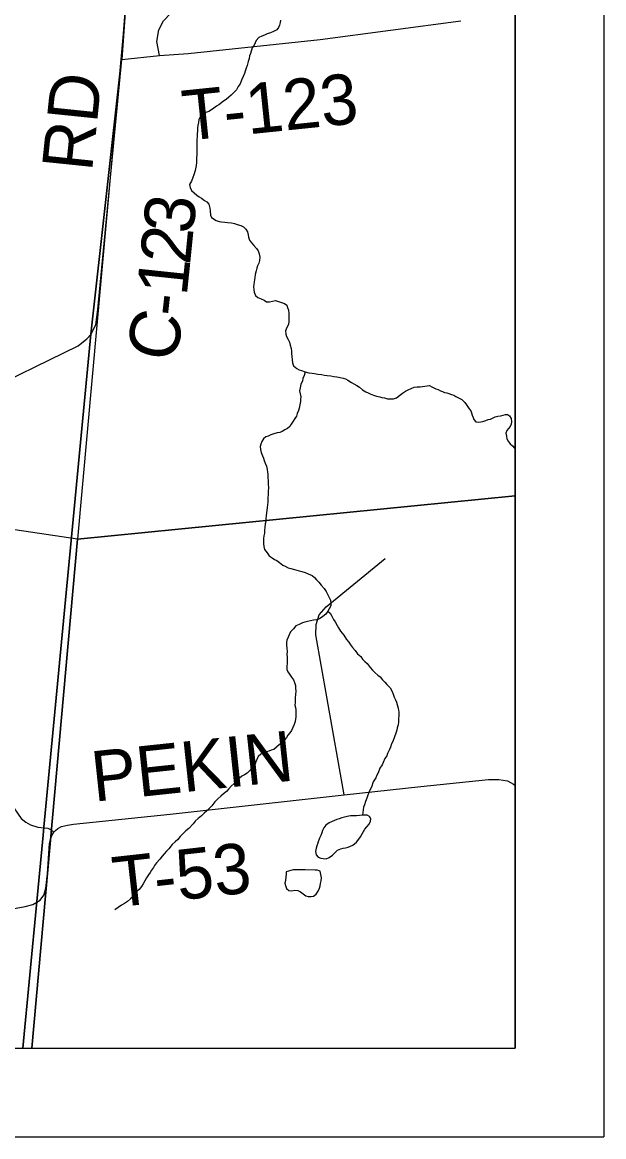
# Model space of a CAD drawing. Extents: x -7.3 to 34, y 0 to 22.
# Drawn here: x 8.344 to 9, y 14 to 15.258 of the extents above; entities that cross this region are included whole.
import ezdxf

# ---------------------------------------------------------------- set-up
doc = ezdxf.new("R2010")
doc.units = 0
for name, color, linetype in [('GM_X_Corporation', 7, 'Continuous'), ('GM_X_County_Road', 7, 'Continuous'), ('GM_X_County_Road_Text', 7, 'Continuous'), ('GM_X_Minor_Lake', 7, 'Continuous'), ('GM_X_Minor_River', 7, 'Continuous'), ('GM_X_Township_Road', 7, 'Continuous'), ('GM_X_Township_Road_Text', 7, 'Continuous'), ('SH_Data', 7, 'Continuous')]:
    doc.layers.add(name, color=color, linetype=linetype)

msp = doc.modelspace()

# ---------------------------------------------------------------- linework, layer by layer
at = {"layer": 'GM_X_Corporation'}
for points in [[(4.3152, 15.5847), (4.2701, 15.1232), (4.2655, 15.0758), (4.2591, 15.0066), (4.246, 14.8644), (4.233, 14.7229), (4.2199, 14.5807), (4.1921, 14.279), (4.1756, 14.1), (8.9, 14.1), (8.9, 19.7858)], [(8.4601, 15.2687), (8.4562, 15.2161), (8.4214, 14.9056), (8.3685, 14.3492), (8.3676, 14.3403), (8.3604, 14.2653), (8.3447, 14.1), (8.9, 14.1), (8.9, 19.3924)], [(4.3152, 15.5847), (4.2701, 15.1232), (4.2655, 15.0758), (4.2591, 15.0066), (4.246, 14.8644), (4.233, 14.7229), (4.2199, 14.5807), (4.1921, 14.279), (4.1756, 14.1), (8.3447, 14.1), (8.3604, 14.2653), (8.3676, 14.3403), (8.3685, 14.3492), (8.4214, 14.9056), (8.4562, 15.2161), (8.4601, 15.2687)]]:
    msp.add_lwpolyline(points, dxfattribs=at)
for points in [[(7.4799, 15.8457), (8.4992, 15.7029), (8.4066, 14.6743), (7.3939, 14.8252)], [(8.9, 14.7231), (8.9, 15.7443), (8.4992, 15.7029), (8.4066, 14.6743)], [(7.3299, 14.1), (8.355, 14.1), (8.4066, 14.6743), (7.3939, 14.8252), (7.354, 14.3269)], [(8.355, 14.1), (8.9, 14.1), (8.9, 14.7231), (8.4066, 14.6743)]]:
    msp.add_lwpolyline(points, close=True, dxfattribs=at)
at = {"layer": 'GM_X_County_Road'}
for points in [[(8.4599, 15.2763), (8.4602, 15.2754), (8.4603, 15.2681), (8.4564, 15.2156)], [(7.8704, 14.526), (7.876, 14.5324), (7.8781, 14.5381), (7.8939, 14.7215), (7.8968, 14.7318), (7.9004, 14.737), (7.9057, 14.74), (7.9114, 14.7411), (7.9173, 14.7411), (7.9598, 14.7363), (8.0106, 14.7293), (8.0376, 14.7266), (8.0458, 14.7274), (8.0546, 14.7289), (8.0834, 14.7403), (8.2135, 14.7969), (8.293, 14.8366), (8.4073, 14.8926), (8.4169, 14.9004), (8.4216, 14.9051), (8.4272, 14.9163), (8.4292, 14.9335), (8.4564, 15.2156)], [(8.3687, 14.2737), (8.3706, 14.2803), (8.3725, 14.2967), (8.3749, 14.331), (8.376, 14.3352), (8.3776, 14.3397), (8.3799, 14.3435)], [(8.0558, 14.2031), (8.1811, 14.2279), (8.3163, 14.254), (8.3475, 14.2599), (8.3559, 14.2622), (8.3606, 14.2648), (8.3644, 14.267), (8.3683, 14.2726), (8.3687, 14.2737)]]:
    msp.add_lwpolyline(points, dxfattribs=at)
at = {"layer": 'GM_X_Minor_Lake'}
for points in [[(8.6777, 14.3315), (8.6775, 14.3311), (8.6763, 14.3281), (8.6755, 14.3255), (8.675, 14.3217), (8.6757, 14.3182), (8.6779, 14.3155), (8.681, 14.3143), (8.6836, 14.3139), (8.687, 14.3134), (8.6905, 14.3149), (8.6939, 14.3178), (8.697, 14.3208), (8.6997, 14.3234), (8.7036, 14.3249), (8.7062, 14.3256), (8.7089, 14.3259), (8.7116, 14.3266), (8.7142, 14.3277), (8.7169, 14.3291), (8.7212, 14.3325), (8.7239, 14.3358), (8.7255, 14.3384), (8.7275, 14.3418), (8.729, 14.3444), (8.7306, 14.3471), (8.7329, 14.3497), (8.7353, 14.3527), (8.7369, 14.356), (8.7373, 14.3587), (8.7358, 14.3614), (8.7332, 14.363), (8.7279, 14.3627)], [(8.7279, 14.3627), (8.7245, 14.3624), (8.7211, 14.3621), (8.7177, 14.3622), (8.7142, 14.3619), (8.7108, 14.3612), (8.7078, 14.3605), (8.7047, 14.3598), (8.7016, 14.3587), (8.699, 14.358), (8.6963, 14.3569), (8.6936, 14.3558), (8.6902, 14.354), (8.6867, 14.3514), (8.6844, 14.3484), (8.6828, 14.3454), (8.682, 14.3428), (8.6808, 14.3398), (8.6796, 14.3368), (8.6777, 14.3315)], [(8.6419, 14.2988), (8.6419, 14.2962), (8.6414, 14.2928), (8.641, 14.2894), (8.6405, 14.286), (8.6412, 14.2833), (8.6423, 14.2802), (8.6449, 14.2779), (8.6483, 14.2774), (8.6517, 14.2781), (8.6551, 14.278), (8.6578, 14.2765), (8.6611, 14.2741), (8.6641, 14.2718), (8.6667, 14.2709), (8.6701, 14.2709), (8.6728, 14.2716), (8.6755, 14.2738), (8.6779, 14.2772), (8.6795, 14.2805), (8.6803, 14.2832), (8.6807, 14.2858), (8.6812, 14.2889), (8.6816, 14.2923), (8.6809, 14.2957), (8.6803, 14.2995), (8.6769, 14.3007), (8.6747, 14.3008)], [(8.6747, 14.3008), (8.6632, 14.301), (8.6598, 14.3011), (8.6564, 14.3012), (8.653, 14.3013), (8.6496, 14.3013), (8.6419, 14.2988)]]:
    msp.add_lwpolyline(points, dxfattribs=at)
at = {"layer": 'GM_X_Minor_River'}
for points in [[(8.6356, 15.2598), (8.6351, 15.2571), (8.6343, 15.2541), (8.6331, 15.2515), (8.6312, 15.2488), (8.6277, 15.247), (8.6243, 15.2456), (8.6204, 15.2445), (8.6174, 15.2431), (8.6143, 15.242), (8.6109, 15.2402), (8.6081, 15.2368), (8.6057, 15.2315), (8.6034, 15.2285), (8.6014, 15.2221), (8.6005, 15.2195), (8.6001, 15.2168), (8.5989, 15.2134), (8.598, 15.2089), (8.5968, 15.2059), (8.5956, 15.2025), (8.5948, 15.1999), (8.5932, 15.1965), (8.5916, 15.1923), (8.59, 15.1882), (8.5877, 15.1852), (8.5857, 15.1814), (8.583, 15.1788)], [(8.583, 15.1788), (8.5799, 15.1751), (8.5772, 15.1729), (8.5741, 15.1703), (8.571, 15.1685), (8.566, 15.1644), (8.5633, 15.1629), (8.5602, 15.1607), (8.5575, 15.1589), (8.5544, 15.157), (8.5502, 15.1552), (8.5475, 15.1541), (8.5452, 15.1512), (8.5432, 15.1478), (8.5428, 15.1444), (8.5423, 15.141), (8.5419, 15.1383), (8.5418, 15.1349), (8.5414, 15.1315), (8.5413, 15.1285), (8.5412, 15.1247), (8.5412, 15.122), (8.5411, 15.1186), (8.541, 15.1159), (8.5409, 15.1121), (8.5412, 15.1076), (8.5408, 15.1049), (8.5407, 15.1019), (8.5407, 15.0992), (8.5402, 15.0958), (8.5393, 15.0901), (8.5377, 15.0852), (8.5365, 15.0822), (8.5349, 15.0784), (8.5329, 15.0743), (8.5336, 15.0709), (8.535, 15.0678), (8.538, 15.0651), (8.541, 15.0624), (8.5436, 15.0604), (8.5462, 15.0592), (8.5496, 15.0565), (8.5522, 15.0549), (8.5544, 15.0522), (8.5558, 15.0476), (8.5562, 15.0446), (8.5564, 15.04), (8.5575, 15.0373), (8.5627, 15.0338), (8.5661, 15.0329), (8.5688, 15.0325), (8.5726, 15.032), (8.5756, 15.0316), (8.5801, 15.0311), (8.5835, 15.0303), (8.5865, 15.0295), (8.5907, 15.0282), (8.5937, 15.0266), (8.5963, 15.0239), (8.5981, 15.0212), (8.5988, 15.0178), (8.5995, 15.0151), (8.6006, 15.0117), (8.6028, 15.0086), (8.6054, 15.0055), (8.6083, 15.0024), (8.6102, 14.9997), (8.6112, 14.9962), (8.6123, 14.9924), (8.6118, 14.9886), (8.611, 14.9856), (8.6094, 14.9826), (8.6086, 14.98), (8.6078, 14.977), (8.6069, 14.9728), (8.6065, 14.969), (8.6056, 14.9648), (8.6052, 14.9618), (8.6051, 14.9592), (8.6054, 14.9557), (8.6057, 14.9531), (8.6072, 14.9492), (8.6098, 14.9469), (8.6135, 14.9453), (8.6169, 14.9441), (8.6195, 14.9421), (8.623, 14.942), (8.6264, 14.9427), (8.6298, 14.9434), (8.6332, 14.9426), (8.6366, 14.9414), (8.64, 14.9402), (8.6426, 14.9382), (8.6433, 14.9355), (8.6444, 14.9328), (8.645, 14.929), (8.645, 14.9256), (8.6448, 14.9199), (8.6444, 14.9165), (8.6424, 14.9131), (8.6412, 14.9094)], [(8.6412, 14.9094), (8.6415, 14.9056), (8.6422, 14.9029), (8.644, 14.8994), (8.6455, 14.8967), (8.6465, 14.8933), (8.6476, 14.8895), (8.6479, 14.8864), (8.6479, 14.8838), (8.6482, 14.8803), (8.6485, 14.8765), (8.6491, 14.8731), (8.6502, 14.87), (8.6539, 14.8669), (8.6566, 14.8653), (8.6592, 14.8645), (8.6633, 14.8629), (8.6675, 14.8621), (8.6713, 14.8616), (8.6739, 14.8612), (8.6777, 14.8603), (8.6815, 14.8599), (8.6849, 14.8594), (8.6879, 14.859), (8.6921, 14.8585), (8.6955, 14.858), (8.6989, 14.8576), (8.7026, 14.8567), (8.706, 14.8559), (8.7087, 14.8551), (8.7113, 14.8535), (8.7154, 14.8511), (8.718, 14.8496), (8.7214, 14.8476), (8.7244, 14.8456), (8.7281, 14.8429), (8.7315, 14.8405), (8.7345, 14.8393), (8.7375, 14.8377), (8.7413, 14.8365), (8.7439, 14.8357), (8.7473, 14.8349), (8.7499, 14.8341), (8.7526, 14.8336), (8.756, 14.8328), (8.7594, 14.8327), (8.7628, 14.8326), (8.7662, 14.8337), (8.7697, 14.8363), (8.7732, 14.8389), (8.7763, 14.8411), (8.7793, 14.8429), (8.7828, 14.8444), (8.7862, 14.8458), (8.7896, 14.8461), (8.7931, 14.846)], [(8.6633, 14.8629), (8.6621, 14.8588), (8.6605, 14.8554), (8.6601, 14.8527), (8.6585, 14.8493), (8.6576, 14.8452), (8.6568, 14.8418), (8.6575, 14.8383), (8.6582, 14.8349), (8.6581, 14.8323), (8.6581, 14.8296), (8.6572, 14.8258), (8.6564, 14.822), (8.6556, 14.8194), (8.6543, 14.816), (8.6535, 14.813), (8.6516, 14.8104), (8.6496, 14.8074), (8.6476, 14.804), (8.6461, 14.8014), (8.6434, 14.7991), (8.6403, 14.7977), (8.6372, 14.7959), (8.6345, 14.7948), (8.6315, 14.7941), (8.628, 14.793), (8.6246, 14.792), (8.6215, 14.7905), (8.6189, 14.7898), (8.6162, 14.7876), (8.6142, 14.7846), (8.6134, 14.7816), (8.6126, 14.7789), (8.6129, 14.7755), (8.6136, 14.7721), (8.615, 14.7682), (8.6161, 14.7655), (8.6171, 14.7629), (8.6182, 14.7602), (8.6197, 14.7567), (8.6203, 14.7529), (8.6207, 14.7499), (8.621, 14.7472), (8.6213, 14.7438), (8.6216, 14.74), (8.6215, 14.7362), (8.6218, 14.7324), (8.6217, 14.7282), (8.6216, 14.7248), (8.6212, 14.721), (8.6211, 14.716), (8.6206, 14.713), (8.6202, 14.71), (8.6201, 14.7066), (8.6197, 14.7039), (8.6192, 14.7005), (8.6188, 14.6975), (8.6187, 14.6941), (8.6182, 14.6914), (8.6178, 14.6876), (8.6173, 14.6846), (8.6173, 14.6812), (8.6168, 14.6781), (8.6164, 14.6751), (8.6163, 14.6721), (8.6163, 14.6694), (8.6166, 14.666), (8.6172, 14.6626), (8.6202, 14.6587), (8.6228, 14.6556), (8.6261, 14.6533), (8.6288, 14.6513), (8.6314, 14.6501), (8.6344, 14.6481), (8.6381, 14.645), (8.6407, 14.6438), (8.6441, 14.6418), (8.6471, 14.641), (8.6513, 14.6402), (8.6539, 14.6394), (8.6565, 14.6385), (8.6596, 14.6377), (8.6633, 14.6365), (8.6667, 14.6353), (8.6712, 14.6333), (8.6738, 14.6309), (8.676, 14.6282), (8.6786, 14.6259), (8.6812, 14.6224), (8.6846, 14.6186), (8.6868, 14.6151), (8.689, 14.6116), (8.6904, 14.6086), (8.6919, 14.6055), (8.6922, 14.6021), (8.6921, 14.599), (8.6905, 14.5956), (8.6889, 14.593), (8.6866, 14.5896), (8.6831, 14.5871), (8.6796, 14.5845)], [(8.7931, 14.846), (8.8035, 14.8475), (8.8061, 14.8463), (8.8083, 14.8451), (8.8106, 14.8439), (8.8132, 14.8431), (8.8159, 14.8415), (8.8181, 14.8407), (8.8204, 14.8399), (8.823, 14.8394), (8.8253, 14.8386), (8.8283, 14.8374), (8.8309, 14.8366), (8.8332, 14.8354), (8.8354, 14.8342), (8.8377, 14.833), (8.8399, 14.8318), (8.8433, 14.8283), (8.8451, 14.826), (8.8469, 14.8236), (8.8484, 14.8213), (8.8502, 14.819), (8.8509, 14.8167), (8.8516, 14.814), (8.8527, 14.8117), (8.8534, 14.8094), (8.8556, 14.8067), (8.8587, 14.8062), (8.8613, 14.8066), (8.8636, 14.8069), (8.8671, 14.8083), (8.8698, 14.8094), (8.8724, 14.8097), (8.8747, 14.8108), (8.8774, 14.8122), (8.8805, 14.8129), (8.8835, 14.8136), (8.8866, 14.8143), (8.8893, 14.815), (8.8916, 14.8149), (8.8938, 14.8133), (8.8956, 14.8103), (8.8959, 14.8068), (8.8958, 14.8042), (8.8946, 14.8015), (8.8927, 14.7993), (8.8907, 14.7967), (8.8895, 14.7937), (8.8902, 14.7906), (8.8909, 14.7876), (8.8923, 14.7849), (8.8945, 14.7818), (8.8971, 14.7794), (8.8993, 14.7771), (8.9, 14.7766)], [(8.6889, 14.593), (8.6915, 14.5907), (8.6934, 14.5872), (8.6952, 14.5838), (8.697, 14.5811), (8.6992, 14.5768), (8.701, 14.5741), (8.7032, 14.5703), (8.7069, 14.566), (8.7098, 14.561), (8.7124, 14.5579), (8.7143, 14.5552), (8.7165, 14.5521), (8.7198, 14.5486), (8.7224, 14.5448), (8.7261, 14.5417), (8.728, 14.539), (8.7305, 14.5363), (8.7332, 14.5339), (8.7365, 14.5293), (8.7391, 14.5266), (8.7417, 14.5239), (8.7454, 14.5207), (8.748, 14.5188), (8.7506, 14.5157), (8.7532, 14.513), (8.7554, 14.5103), (8.7591, 14.5064), (8.7613, 14.5025), (8.7624, 14.4995), (8.7638, 14.496), (8.7653, 14.493), (8.7663, 14.4903), (8.7674, 14.4861), (8.7681, 14.4834), (8.7688, 14.4792), (8.769, 14.4754), (8.7686, 14.4716), (8.7685, 14.4678), (8.7681, 14.4648), (8.7672, 14.4614), (8.7668, 14.4587), (8.7656, 14.4553), (8.764, 14.4512), (8.762, 14.4459), (8.7608, 14.4433), (8.7595, 14.4395), (8.7583, 14.4369), (8.756, 14.4324), (8.7552, 14.4297), (8.7532, 14.4267), (8.7512, 14.4222), (8.75, 14.4196), (8.7476, 14.4158), (8.7456, 14.4106), (8.7441, 14.4079), (8.7429, 14.4049), (8.7401, 14.4004), (8.7381, 14.3944), (8.7361, 14.391), (8.7349, 14.3884), (8.7341, 14.3854), (8.7329, 14.382), (8.7313, 14.3782), (8.7301, 14.3744), (8.7292, 14.3718), (8.7279, 14.3627)], [(8.6796, 14.5845), (8.6762, 14.5834), (8.6728, 14.5827), (8.6693, 14.582), (8.6659, 14.5814), (8.6629, 14.5807), (8.6602, 14.58), (8.6564, 14.5778), (8.6529, 14.5763), (8.6502, 14.573), (8.6467, 14.5696), (8.6451, 14.5662), (8.6439, 14.5636), (8.6427, 14.5602), (8.6423, 14.5575), (8.6422, 14.5541), (8.6425, 14.5515), (8.6428, 14.5473), (8.6427, 14.5446), (8.643, 14.5412), (8.643, 14.5374), (8.6429, 14.5344), (8.6424, 14.5306), (8.6427, 14.5271), (8.6438, 14.5245), (8.6457, 14.5218), (8.6479, 14.5187), (8.6501, 14.5156), (8.6511, 14.5125), (8.6522, 14.5091), (8.6525, 14.506), (8.6528, 14.5026), (8.6524, 14.4988), (8.6519, 14.4954), (8.6518, 14.4928), (8.6518, 14.4901), (8.6517, 14.4871), (8.6524, 14.4844), (8.6527, 14.4817), (8.6527, 14.4787), (8.6526, 14.4737), (8.6525, 14.4711), (8.6521, 14.4684), (8.6509, 14.465), (8.6493, 14.4617), (8.6477, 14.4583), (8.6461, 14.4556), (8.6438, 14.453), (8.6422, 14.4504), (8.6375, 14.4452), (8.6341, 14.4422), (8.631, 14.4396), (8.6279, 14.4371), (8.6248, 14.436), (8.6221, 14.4349), (8.6195, 14.4342), (8.6164, 14.4331), (8.6133, 14.4317), (8.6103, 14.4291), (8.6087, 14.4257), (8.6075, 14.4231), (8.6063, 14.4197), (8.6039, 14.4171), (8.6012, 14.4137), (8.5977, 14.4104), (8.595, 14.4085), (8.5919, 14.4067), (8.5888, 14.4041), (8.5857, 14.4007), (8.583, 14.3985), (8.5796, 14.3955), (8.5768, 14.3922), (8.5745, 14.3896), (8.571, 14.387), (8.5683, 14.3844), (8.5648, 14.3811), (8.5613, 14.3777), (8.5578, 14.3732), (8.5555, 14.3706), (8.5524, 14.3676), (8.5493, 14.3651), (8.5462, 14.3621), (8.5424, 14.3591), (8.5393, 14.3562), (8.5369, 14.3532), (8.5322, 14.3476), (8.5288, 14.345), (8.5249, 14.3413), (8.5222, 14.3387), (8.5198, 14.3353), (8.5167, 14.3327), (8.5133, 14.3297), (8.5094, 14.3249), (8.507, 14.3223), (8.5043, 14.3193), (8.502, 14.3167), (8.4993, 14.3133), (8.4957, 14.3089), (8.4934, 14.3062), (8.4922, 14.3036), (8.4899, 14.3006)], [(8.4899, 14.3006), (8.4883, 14.298), (8.4867, 14.2954), (8.4844, 14.292), (8.4824, 14.2886), (8.4804, 14.2852), (8.4785, 14.2822), (8.4761, 14.2789), (8.4734, 14.2767), (8.4715, 14.2737), (8.4691, 14.2711), (8.4664, 14.2685), (8.4629, 14.2655), (8.4595, 14.2633), (8.456, 14.2611), (8.4522, 14.2585), (8.4487, 14.2559)]]:
    msp.add_lwpolyline(points, dxfattribs=at)
at = {"layer": 'GM_X_Township_Road'}
for points in [[(8.4991, 15.2202), (8.496, 15.236), (8.498, 15.2488), (8.5034, 15.2591), (8.5354, 15.2929), (8.5493, 15.307), (8.5573, 15.3172), (8.5625, 15.3244), (8.5665, 15.3336), (8.5716, 15.3445), (8.5773, 15.3659), (8.5801, 15.376), (8.5821, 15.3838), (8.5838, 15.3896), (8.5863, 15.395), (8.5918, 15.4005), (8.5996, 15.4057), (8.6113, 15.414)], [(8.4564, 15.2156), (8.4991, 15.2202), (8.5311, 15.2224), (8.6803, 15.238), (8.8388, 15.2593)], [(8.7074, 14.3857), (8.6753, 14.5664), (8.6757, 14.5779), (8.6792, 14.5889), (8.6869, 14.5978), (8.7535, 14.6525)], [(8.3974, 14.352), (8.4018, 14.3527), (8.5111, 14.3641), (8.7074, 14.3857), (8.7938, 14.3952), (8.87, 14.4029), (8.8817, 14.403), (8.8915, 14.4016), (8.8984, 14.3977), (8.9, 14.3962)], [(8.2633, 14.3728), (8.2816, 14.3797), (8.2868, 14.3818), (8.2941, 14.3833), (8.3046, 14.3833), (8.3124, 14.3828), (8.3181, 14.3816), (8.3234, 14.3802), (8.3283, 14.3774), (8.3338, 14.3721), (8.3396, 14.3638), (8.343, 14.359), (8.3481, 14.3549), (8.3536, 14.3521), (8.3618, 14.3493), (8.3687, 14.3487), (8.3729, 14.3481), (8.3767, 14.3463), (8.3799, 14.3435)], [(8.3799, 14.3435), (8.3817, 14.3457), (8.3844, 14.3478), (8.3884, 14.35), (8.3952, 14.3517), (8.3974, 14.352)]]:
    msp.add_lwpolyline(points, dxfattribs=at)
at = {"layer": 'SH_Data'}
for p, q in [((9, 21), (9, 14)), ((8.9, 20.9), (8.9, 14.1)), ((2.1, 14.1), (8.9, 14.1)), ((2, 14), (9, 14))]:
    msp.add_line(p, q, dxfattribs=at)

# ---------------------------------------------------------------- texts
at = {"layer": 'GM_X_County_Road_Text'}
for s, height, rotation, p in [('RD', 0.05682, 84.0953, (8.4227, 15.0881)), ('3', 0.0568, 84.3761, (8.5368, 15.0178)), ('2', 0.0568, 84.3036, (8.5333, 14.9829)), ('1', 0.0568, 83.9845, (8.5296, 14.9477)), ('-', 0.0568, 83.5223, (8.5269, 14.924)), ('C', 0.0568, 77.1177, (8.5153, 14.8717))]:
    msp.add_text(s, height=height, rotation=rotation, dxfattribs=at).set_placement(p)
at = {"layer": 'GM_X_Township_Road_Text'}
for s, rotation, p in [('T-123', 5.9128, (8.5276, 15.1236)), ('PEKIN', 6.0826, (8.4252, 14.3779)), ('T-53', 6.3798, (8.4493, 14.2587))]:
    msp.add_text(s, height=0.05682, rotation=rotation, dxfattribs=at).set_placement(p)

doc.saveas('drawing.dxf')
